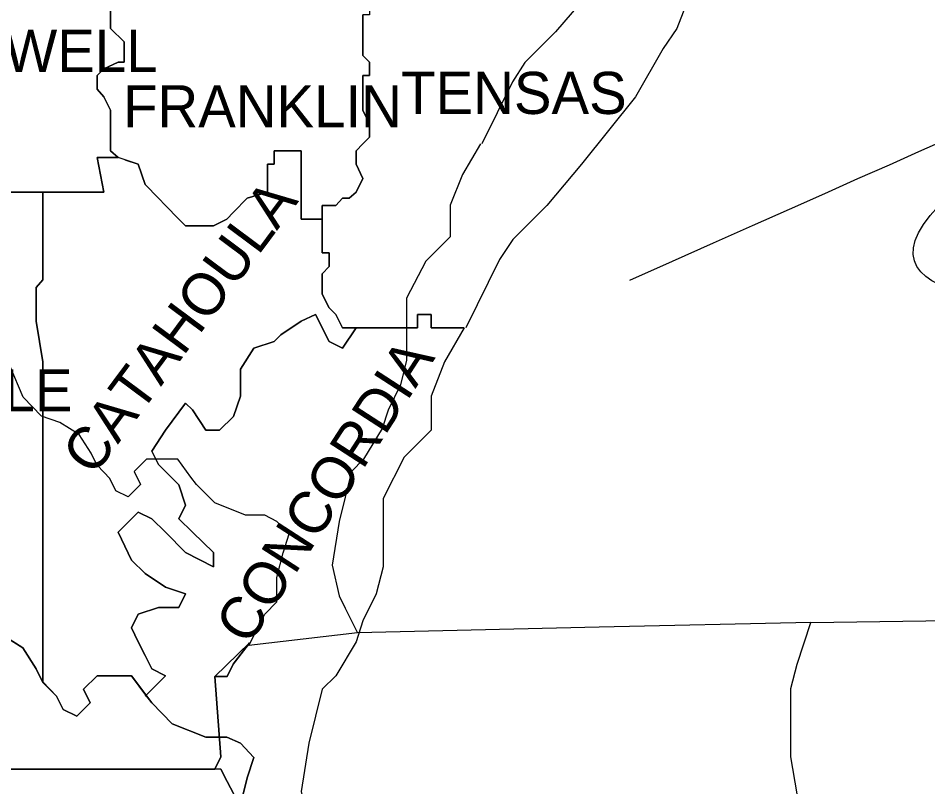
# Model space of a CAD drawing. Extents: x 0.19 to 2.82, y 0.04 to 1.79.
# Drawn here: x 2.3524 to 2.4634, y 1.5609 to 1.6548 of the extents above; entities that cross this region are included whole.
import ezdxf

# ---------------------------------------------------------------- set-up
doc = ezdxf.new("R2010")
doc.units = 0
for name, color, linetype in [('Annotation', 7, 'Continuous'), ('Dist03', 7, 'Continuous'), ('Dist08', 7, 'Continuous'), ('Dist58', 7, 'Continuous'), ('Dist61', 7, 'Continuous'), ('Dist62', 7, 'Continuous'), ('Standard Info', 7, 'Continuous')]:
    doc.layers.add(name, color=color, linetype=linetype)

msp = doc.modelspace()

# ---------------------------------------------------------------- linework, layer by layer
at = {"layer": 'Annotation'}
msp.add_open_spline([(2.54158, 1.67375), (2.53002, 1.63912), (2.4977, 1.61554), (2.42701, 1.62272), (2.54158, 1.67375), (2.42701, 1.62272)], degree=3, dxfattribs=at)
at = {"layer": 'Dist03'}
for points in [[(2.37715, 1.56308), (2.3469, 1.56308)], [(2.3829, 1.53617), (2.38099, 1.53892), (2.38099, 1.54267), (2.38165, 1.548), (2.38165, 1.551), (2.38099, 1.554), (2.37949, 1.55858), (2.3779, 1.56158), (2.37715, 1.56308)]]:
    msp.add_lwpolyline(points, dxfattribs=at)
at = {"layer": 'Dist08'}
for points in [[(2.36207, 1.60008), (2.36132, 1.60167), (2.35982, 1.60392), (2.35749, 1.60542), (2.35524, 1.60617), (2.35299, 1.6085), (2.3514, 1.61225), (2.3499, 1.61525), (2.3469, 1.61675), (2.3439, 1.61908), (2.34165, 1.62133), (2.34082, 1.62358), (2.33932, 1.62583), (2.33707, 1.62808), (2.33632, 1.62883), (2.33557, 1.63192), (2.33632, 1.63417), (2.33632, 1.63717), (2.33707, 1.64092), (2.33757, 1.644)], [(2.37349, 1.59875), (2.3719, 1.60092), (2.36807, 1.60092), (2.36657, 1.59942), (2.36732, 1.59783), (2.36582, 1.59633), (2.36432, 1.59708), (2.36357, 1.59858), (2.36207, 1.60017)], [(2.38057, 1.57817), (2.38249, 1.582), (2.38399, 1.5835), (2.38399, 1.5865), (2.38474, 1.5895), (2.38549, 1.59183), (2.38399, 1.59333), (2.38249, 1.59408), (2.38015, 1.59408), (2.3764, 1.59558), (2.37415, 1.59783), (2.37349, 1.59875)], [(2.3764, 1.57442), (2.3779, 1.57442), (2.37865, 1.57592), (2.38065, 1.5785)], [(2.3764, 1.56308), (2.37715, 1.56458), (2.3764, 1.57442)], [(2.3424, 1.57292), (2.3424, 1.57067), (2.3439, 1.56917), (2.3454, 1.56758), (2.3454, 1.56308), (2.3764, 1.56308)]]:
    msp.add_lwpolyline(points, dxfattribs=at)
at = {"layer": 'Dist58'}
for points in [[(2.43465, 1.67875), (2.4339, 1.6765), (2.4324, 1.67275), (2.4309, 1.6705), (2.42782, 1.66517), (2.42482, 1.66142), (2.42182, 1.65758), (2.41799, 1.65308), (2.41424, 1.64933), (2.41274, 1.647), (2.40899, 1.63942)], [(2.36207, 1.60008), (2.36132, 1.60167), (2.35982, 1.60392), (2.35749, 1.60542), (2.35524, 1.60617), (2.35299, 1.6085), (2.3514, 1.61225), (2.3499, 1.61525), (2.3469, 1.61675), (2.3439, 1.61908), (2.34165, 1.62133), (2.34082, 1.62358), (2.33932, 1.62583), (2.33707, 1.62808), (2.33632, 1.62883), (2.33557, 1.63192), (2.33632, 1.63417), (2.33632, 1.63717), (2.33707, 1.64092), (2.33757, 1.644)], [(2.40882, 1.63942), (2.40665, 1.63567), (2.40515, 1.63192), (2.40515, 1.62808), (2.40215, 1.62508), (2.39982, 1.62058), (2.39982, 1.613), (2.39907, 1.61), (2.39757, 1.60692), (2.39682, 1.60467), (2.39457, 1.60092), (2.39307, 1.59942), (2.39157, 1.59333), (2.39074, 1.588), (2.39157, 1.58425), (2.39232, 1.58275), (2.39382, 1.57975)], [(2.37349, 1.59875), (2.3719, 1.60092), (2.36807, 1.60092), (2.36657, 1.59942), (2.36732, 1.59783), (2.36582, 1.59633), (2.36432, 1.59708), (2.36357, 1.59858), (2.36207, 1.60017)], [(2.38057, 1.57817), (2.38249, 1.582), (2.38399, 1.5835), (2.38399, 1.5865), (2.38474, 1.5895), (2.38549, 1.59183), (2.38399, 1.59333), (2.38249, 1.59408), (2.38015, 1.59408), (2.3764, 1.59558), (2.37415, 1.59783), (2.37349, 1.59875)], [(2.39382, 1.57975), (2.38057, 1.57817)]]:
    msp.add_lwpolyline(points, dxfattribs=at)
at = {"layer": 'Dist61'}
msp.add_line((2.3764, 1.57442), (2.38065, 1.5785), dxfattribs=at)
for points in [[(2.42332, 1.58042), (2.39382, 1.57975)], [(2.44915, 1.581), (2.42332, 1.58042)], [(2.44674, 1.55325), (2.44749, 1.5555), (2.44749, 1.56008), (2.44674, 1.56458), (2.44674, 1.56983), (2.44674, 1.57292), (2.44749, 1.57592), (2.44915, 1.581)], [(2.39382, 1.57975), (2.38057, 1.57817)], [(2.38065, 1.5785), (2.37865, 1.57592), (2.3779, 1.57442), (2.3764, 1.57442)], [(2.38049, 1.57825), (2.37865, 1.57592), (2.3779, 1.57442), (2.3764, 1.57442)], [(2.3764, 1.57442), (2.37715, 1.56458), (2.3764, 1.56308)], [(2.37715, 1.56308), (2.3779, 1.56158), (2.37949, 1.55858), (2.38099, 1.554), (2.38165, 1.551), (2.38165, 1.548), (2.38099, 1.54267), (2.38099, 1.53892), (2.3829, 1.53617)]]:
    msp.add_lwpolyline(points, dxfattribs=at)
at = {"layer": 'Dist62'}
msp.add_line((2.44915, 1.581), (2.46715, 1.58125), dxfattribs=at)
msp.add_lwpolyline([(2.44674, 1.55325), (2.44749, 1.5555), (2.44749, 1.56008), (2.44674, 1.56458), (2.44674, 1.56983), (2.44674, 1.57292), (2.44749, 1.57592), (2.44915, 1.581)], dxfattribs=at)
at = {"layer": 'Standard Info'}
for points in [[(2.3953, 1.65938), (2.3953, 1.65516), (2.39447, 1.65516), (2.39447, 1.65021), (2.3953, 1.64939), (2.3953, 1.64774), (2.39447, 1.64774), (2.39447, 1.64352), (2.3953, 1.64187), (2.3953, 1.64022), (2.39447, 1.6394), (2.39365, 1.63857), (2.39365, 1.63692), (2.39447, 1.63518), (2.39365, 1.63353), (2.39282, 1.6328), (2.392, 1.6328), (2.39117, 1.63188), (2.38952, 1.63188), (2.38952, 1.63023)], [(2.43526, 1.66021), (2.43444, 1.65773), (2.43279, 1.65351), (2.43114, 1.65104), (2.42775, 1.64517), (2.42445, 1.64105), (2.42115, 1.63692), (2.41693, 1.63188), (2.4128, 1.62776), (2.41115, 1.62528), (2.40703, 1.61694)], [(2.36367, 1.65608), (2.36367, 1.65351), (2.36532, 1.65186), (2.36532, 1.64939), (2.36459, 1.64939), (2.36285, 1.64856), (2.36202, 1.64774), (2.36202, 1.64609), (2.36285, 1.64517), (2.36367, 1.64352), (2.36367, 1.64105), (2.36367, 1.63857), (2.36459, 1.63775)], [(2.38952, 1.63023), (2.38695, 1.63023), (2.38695, 1.63857), (2.38365, 1.63857), (2.38365, 1.63692), (2.38283, 1.63692), (2.38283, 1.63518), (2.38283, 1.63353), (2.38035, 1.6328), (2.3787, 1.63106), (2.37788, 1.63023), (2.37623, 1.62941), (2.37458, 1.62941), (2.37284, 1.62941), (2.37201, 1.63023), (2.37036, 1.63188), (2.36954, 1.6328), (2.36789, 1.63445), (2.36706, 1.63692), (2.36459, 1.63775), (2.36367, 1.63857), (2.36367, 1.64105), (2.36367, 1.64352), (2.36285, 1.64517), (2.36202, 1.64609), (2.36202, 1.64774), (2.36285, 1.64856), (2.36459, 1.64939), (2.36532, 1.64939), (2.36532, 1.65186), (2.36367, 1.65351), (2.36367, 1.65608)], [(2.40685, 1.61694), (2.40281, 1.61694), (2.40281, 1.61859), (2.40116, 1.61859), (2.40116, 1.61694), (2.39951, 1.61694), (2.39447, 1.61694), (2.392, 1.61694), (2.39117, 1.61859), (2.39035, 1.61941), (2.38952, 1.62106), (2.38952, 1.62189), (2.38952, 1.62354), (2.39035, 1.62446), (2.39035, 1.62611), (2.38952, 1.62611), (2.38952, 1.63188), (2.39117, 1.63188), (2.392, 1.6328), (2.39282, 1.6328), (2.39365, 1.63353), (2.39447, 1.63518), (2.39365, 1.63692), (2.39365, 1.63857), (2.39447, 1.6394), (2.3953, 1.64022), (2.3953, 1.64187), (2.39447, 1.64352), (2.39447, 1.64774), (2.3953, 1.64774), (2.3953, 1.64939), (2.39447, 1.65021), (2.39447, 1.65516)], [(2.36541, 1.63747), (2.36706, 1.63692), (2.36789, 1.63445), (2.36954, 1.6328), (2.37036, 1.63188), (2.37201, 1.63023), (2.37284, 1.62941), (2.37458, 1.62941), (2.37623, 1.62941), (2.37788, 1.63023), (2.3787, 1.63106), (2.38035, 1.6328), (2.38283, 1.63353), (2.38283, 1.63518), (2.38283, 1.63692), (2.38365, 1.63692), (2.38365, 1.63857), (2.38695, 1.63857), (2.38695, 1.63023), (2.38952, 1.63023)], [(2.36459, 1.63775), (2.36202, 1.63775), (2.36285, 1.63353), (2.35542, 1.63353), (2.33131, 1.63353)], [(2.35542, 1.63353), (2.36285, 1.63353), (2.36202, 1.63775), (2.36459, 1.63775)], [(2.33131, 1.63353), (2.35542, 1.63353)], [(2.35542, 1.63353), (2.35542, 1.62281), (2.3546, 1.62189), (2.3546, 1.61776), (2.35542, 1.61281), (2.35542, 1.57367)], [(2.35542, 1.57367), (2.35542, 1.61281), (2.3546, 1.61776), (2.3546, 1.62189), (2.35542, 1.62281), (2.35542, 1.63353)], [(2.38952, 1.63023), (2.38952, 1.62611), (2.39035, 1.62611), (2.39035, 1.62446), (2.38952, 1.62354), (2.38952, 1.62189), (2.38952, 1.62106), (2.39035, 1.61941), (2.39117, 1.61859), (2.392, 1.61694), (2.39365, 1.61694)], [(2.35542, 1.57367), (2.3546, 1.57532), (2.35295, 1.57789), (2.35038, 1.57954), (2.3479, 1.58036), (2.34543, 1.58284), (2.34369, 1.58696), (2.34204, 1.59026), (2.33874, 1.59201), (2.33544, 1.59448), (2.33296, 1.59696), (2.33205, 1.59952), (2.3304, 1.60191), (2.32792, 1.60447), (2.3271, 1.6053), (2.32627, 1.6086), (2.3271, 1.61116), (2.3271, 1.61446), (2.32792, 1.61859), (2.32847, 1.62189)], [(2.39365, 1.61694), (2.392, 1.61446), (2.39035, 1.61529), (2.3887, 1.61859), (2.38695, 1.61776), (2.38448, 1.61611), (2.38365, 1.61529), (2.38118, 1.61446), (2.37953, 1.6119), (2.37953, 1.61025), (2.37953, 1.6086), (2.3787, 1.60612), (2.37696, 1.60447), (2.37531, 1.60447), (2.37366, 1.60695), (2.37284, 1.60777), (2.37036, 1.60447), (2.36871, 1.60191), (2.36954, 1.60026), (2.37201, 1.59778), (2.37284, 1.59531), (2.37201, 1.59366), (2.37366, 1.59201), (2.37623, 1.58953), (2.37623, 1.58779), (2.37284, 1.58953), (2.37036, 1.59201), (2.36871, 1.59366), (2.36706, 1.59448), (2.36459, 1.59201), (2.36624, 1.58861), (2.36789, 1.58696), (2.37036, 1.58531), (2.37284, 1.58449), (2.37201, 1.58284), (2.36954, 1.58284), (2.36706, 1.58201), (2.36624, 1.58036), (2.36706, 1.57862), (2.36789, 1.57697), (2.36871, 1.57532), (2.37036, 1.5745), (2.36789, 1.57202)], [(2.36789, 1.57202), (2.37036, 1.5745), (2.36871, 1.57532), (2.36789, 1.57697), (2.36706, 1.57862), (2.36624, 1.58036), (2.36706, 1.58201), (2.36954, 1.58284), (2.37201, 1.58284), (2.37284, 1.58449), (2.37036, 1.58531), (2.36789, 1.58696), (2.36624, 1.58861), (2.36459, 1.59201), (2.36706, 1.59448), (2.36871, 1.59366), (2.37036, 1.59201), (2.37284, 1.58953), (2.37623, 1.58779), (2.37623, 1.58953), (2.37366, 1.59201), (2.37201, 1.59366), (2.37284, 1.59531), (2.37201, 1.59778), (2.36954, 1.60026), (2.36871, 1.60191), (2.37036, 1.60447), (2.37284, 1.60777), (2.37366, 1.60695), (2.37531, 1.60447), (2.37696, 1.60447), (2.3787, 1.60612), (2.37953, 1.6086), (2.37953, 1.61025), (2.37953, 1.6119), (2.38118, 1.61446), (2.38365, 1.61529), (2.38448, 1.61611), (2.38695, 1.61776), (2.3887, 1.61859), (2.39035, 1.61529), (2.392, 1.61446), (2.39365, 1.61694)], [(2.39365, 1.61694), (2.39951, 1.61694), (2.40116, 1.61694), (2.40116, 1.61859), (2.40281, 1.61859), (2.40281, 1.61694), (2.40685, 1.61694)], [(2.40685, 1.61694), (2.40446, 1.61281), (2.40281, 1.6086), (2.40281, 1.60447), (2.39951, 1.60117), (2.39695, 1.59613), (2.39695, 1.58779), (2.39612, 1.58449), (2.39447, 1.58119), (2.39365, 1.57862), (2.39117, 1.5745), (2.38952, 1.57285), (2.38787, 1.56625), (2.38695, 1.56038), (2.38787, 1.55626), (2.3887, 1.55451), (2.39035, 1.55121)], [(2.35111, 1.57908), (2.35295, 1.57789), (2.3546, 1.57532), (2.35542, 1.57367), (2.35707, 1.57202), (2.3579, 1.57037), (2.35955, 1.56955), (2.3612, 1.5712), (2.36037, 1.57285), (2.36202, 1.5745), (2.36624, 1.5745), (2.36871, 1.5712), (2.37119, 1.56863), (2.37531, 1.56698), (2.37788, 1.56698), (2.37953, 1.56625), (2.38118, 1.56451), (2.38035, 1.56203), (2.37953, 1.55873), (2.37953, 1.55534), (2.37788, 1.55369), (2.37586, 1.54975)], [(2.36798, 1.57211), (2.36624, 1.5745), (2.36202, 1.5745), (2.36037, 1.57285), (2.3612, 1.5712), (2.35955, 1.56955), (2.3579, 1.57037), (2.35707, 1.57202), (2.35542, 1.57376)], [(2.37577, 1.54956), (2.37788, 1.55369), (2.37953, 1.55534), (2.37953, 1.55873), (2.38035, 1.56203), (2.38118, 1.56451), (2.37953, 1.56625), (2.37788, 1.56698), (2.37531, 1.56698), (2.37119, 1.56863), (2.36871, 1.5712), (2.36798, 1.57211)]]:
    msp.add_lwpolyline(points, dxfattribs=at)

# ---------------------------------------------------------------- texts
for s, p in [('CALDWELL', (2.33231, 1.6482)), ('TENSAS', (2.39915, 1.64306)), ('FRANKLIN', (2.3652, 1.64142)), ('LASALLE', (2.32918, 1.60676))]:
    msp.add_text(s, height=0.005147, dxfattribs=at).set_placement(p)
for s, rotation, p in [('CATAHOULA', 53.3344, (2.36159, 1.5987)), ('CONCORDIA', 57.0945, (2.38053, 1.57802))]:
    msp.add_text(s, height=0.005147, rotation=rotation, dxfattribs=at).set_placement(p)

doc.saveas('drawing.dxf')
